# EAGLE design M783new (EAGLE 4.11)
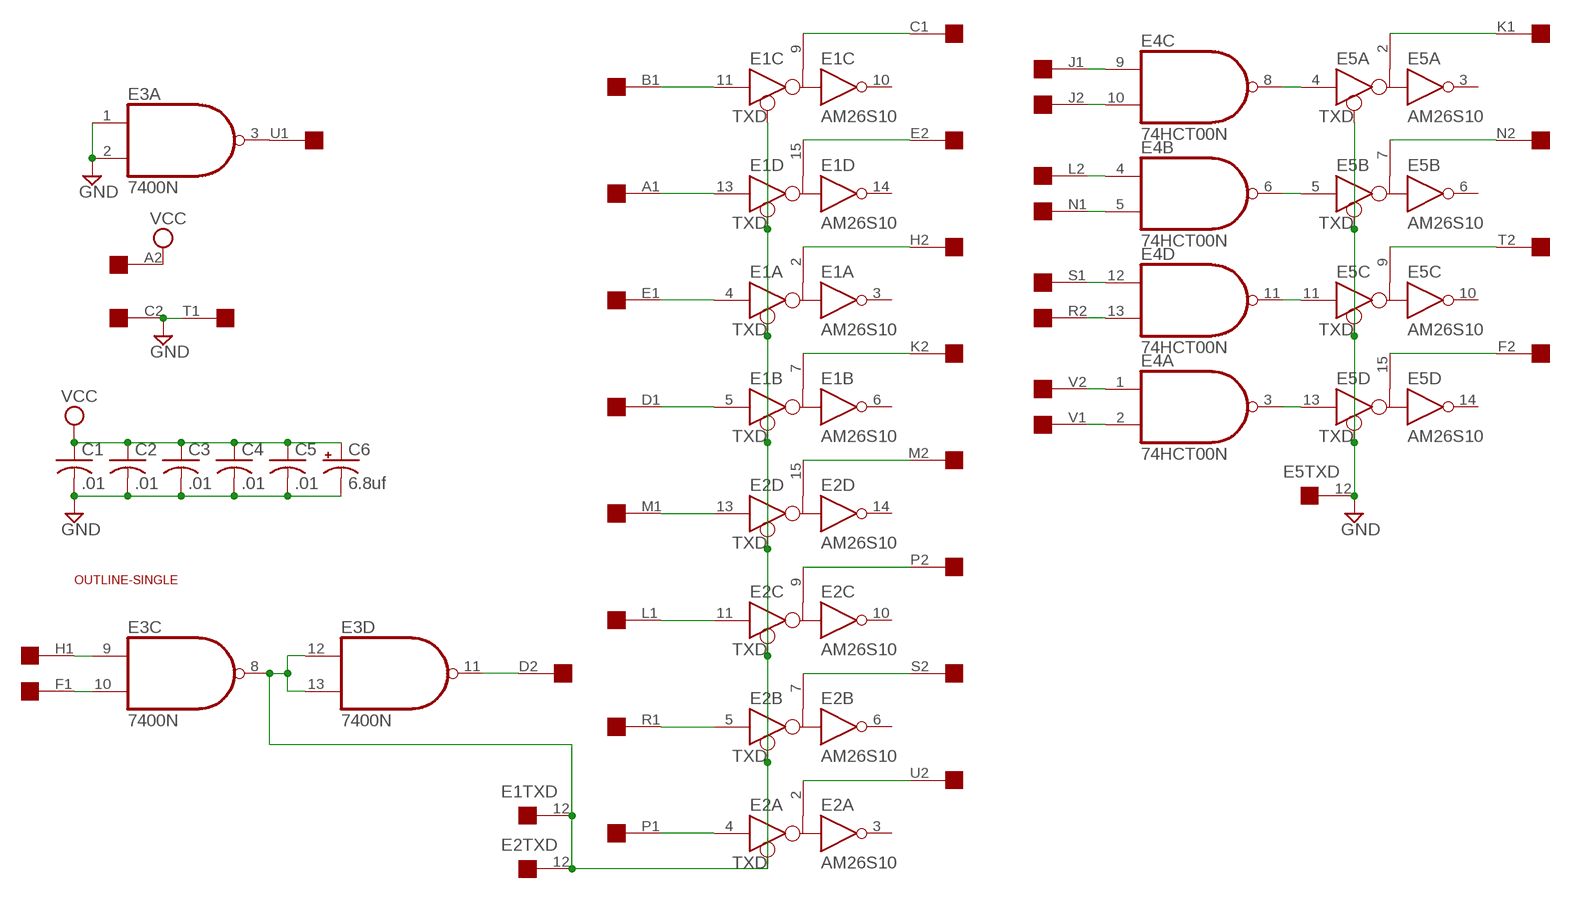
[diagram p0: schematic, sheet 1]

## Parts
C1  .01  C-US050-025X075  [C050-025X075]
C2  .01  C-US050-025X075  [C050-025X075]
C3  .01  C-US050-025X075  [C050-025X075]
C4  .01  C-US050-025X075  [C050-025X075]
C5  .01  C-US050-025X075  [C050-025X075]
C6  6.8uf  CPOL-USE15-5AXIAL  [E15-5]
E1  AM26S10  [DIL16]
E2  AM26S10  [DIL16]
E3  7400N  [DIL14]
E4  74HCT00N  [DIL14]
E5  AM26S10  [DIL16]
U$1  SINGLE  [EDGE-CON2]
U$2  OUTLINE-SINGLE  [SINGLE]

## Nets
GND: C1.2 C2.2 C3.2 C4.2 C5.2 C6.- E3.1(A:I0) E3.2(A:I1) E5.12(TXD:TXD) U$1.C2 U$1.T1
N$1: E3.3(A:O) U$1.U1
N$2: E1.12(TXD:TXD) E2.12(TXD:TXD) E3.8(C:O) E3.12(D:I0) E3.13(D:I1)
N$3: E2.15(D:B) U$1.M2
N$4: E2.9(C:B) U$1.P2
N$5: E2.4(A:D) U$1.P1
N$6: E2.5(B:D) U$1.R1
N$7: E2.7(B:B) U$1.S2
N$8: E2.11(C:D) U$1.L1
N$9: E2.2(A:B) U$1.U2
N$10: E2.13(D:D) U$1.M1
N$11: E1.9(C:B) U$1.C1
N$12: E1.11(C:D) U$1.B1
N$13: E1.15(D:B) U$1.E2
N$14: E1.13(D:D) U$1.A1
N$15: E1.2(A:B) U$1.H2
N$16: E1.4(A:D) U$1.E1
N$17: E1.7(B:B) U$1.K2
N$18: E1.5(B:D) U$1.D1
N$19: E3.11(D:O) U$1.D2
N$20: E5.7(B:B) U$1.N2
N$21: E5.9(C:B) U$1.T2
N$22: E5.15(D:B) U$1.F2
N$23: E5.2(A:B) U$1.K1
N$24: E4.9(C:I0) U$1.J1
N$25: E4.10(C:I1) U$1.J2
N$26: E4.4(B:I0) U$1.L2
N$27: E4.5(B:I1) U$1.N1
N$28: E4.12(D:I0) U$1.S1
N$29: E4.13(D:I1) U$1.R2
N$31: E3.9(C:I0) U$1.H1
N$32: E3.10(C:I1) U$1.F1
N$33: E4.1(A:I0) U$1.V2
N$34: E4.2(A:I1) U$1.V1
N$35: E4.8(C:O) E5.4(A:D)
N$36: E4.6(B:O) E5.5(B:D)
N$37: E4.11(D:O) E5.11(C:D)
N$38: E4.3(A:O) E5.13(D:D)
VCC: C1.1 C2.1 C3.1 C4.1 C5.1 C6.+ U$1.A2
Unconnected: E1.3(A:R) E1.6(B:R) E1.10(C:R) E1.14(D:R) E2.3(A:R) E2.6(B:R) E2.10(C:R) E2.14(D:R) E3.4(B:I0) E3.5(B:I1) E3.6(B:O) E5.3(A:R) E5.6(B:R) E5.10(C:R) E5.14(D:R) U$1.B2

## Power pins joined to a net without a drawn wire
GND: E1.1(GND:GND) E1.8(PWR:GND) E2.1(GND:GND) E2.8(PWR:GND) E3.7(P:GND) E4.7(P:GND) E5.1(GND:GND) E5.8(PWR:GND)
VCC: E1.16(PWR:VCC) E2.16(PWR:VCC) E3.14(P:VCC) E4.14(P:VCC) E5.16(PWR:VCC)

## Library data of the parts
C1-C5 = rcl:C-US: CAPACITOR, American symbol
C6 = rcl:CPOL-US: POLARIZED CAPACITOR, American symbol
E1 E2 E5 = dec-con:AM26S10: Bus Transceiver
E3 E4 = 74xx-jameco:74*00: Quad 2-input NAND gate
U$1 = dec-con:SINGLE: Single-Height DEC board
U$2 = dec-con:OUTLINE-*: Board outlines for DEC boards.

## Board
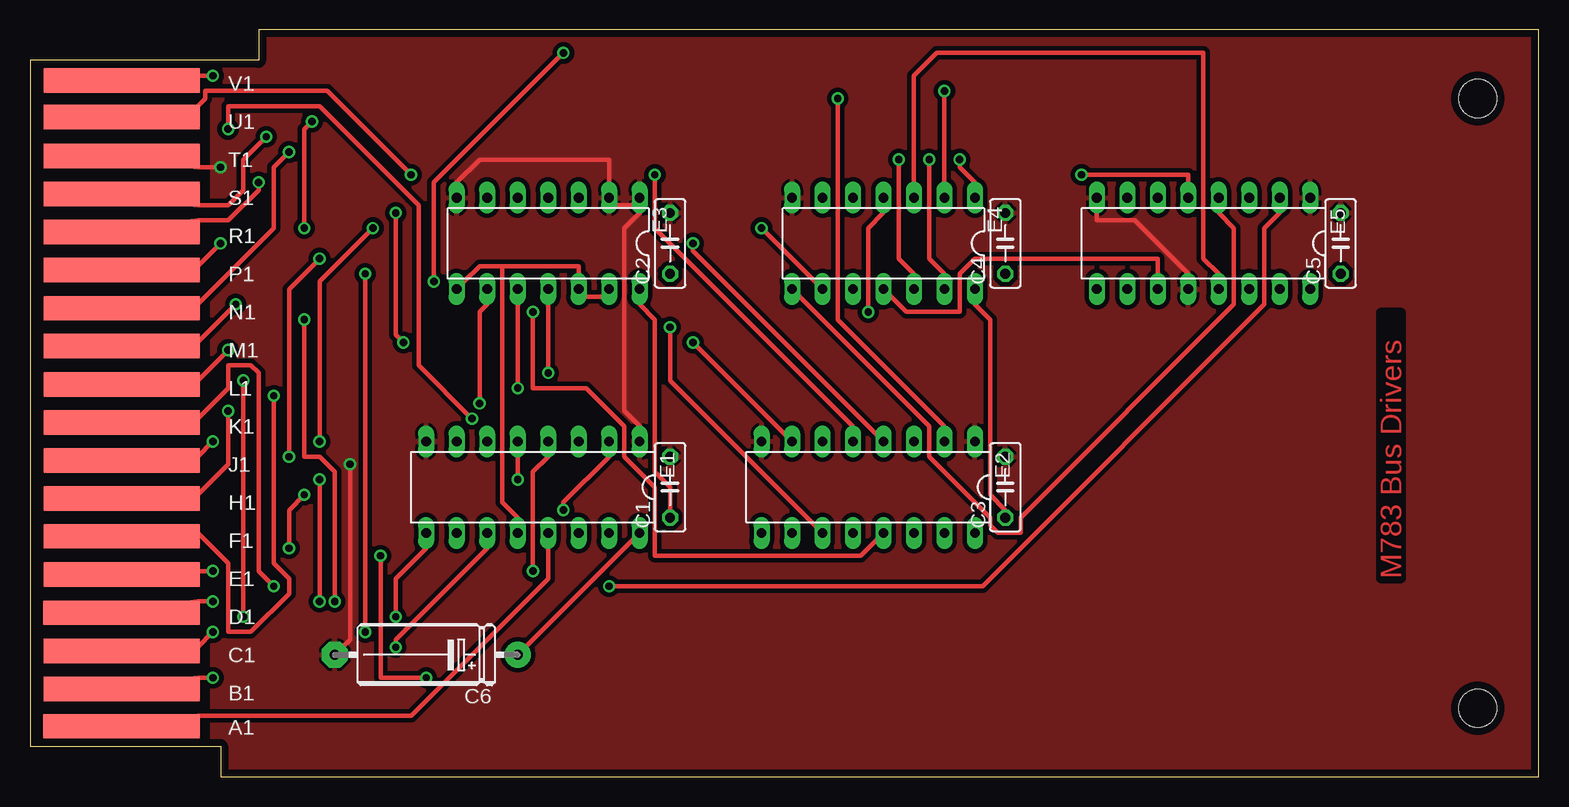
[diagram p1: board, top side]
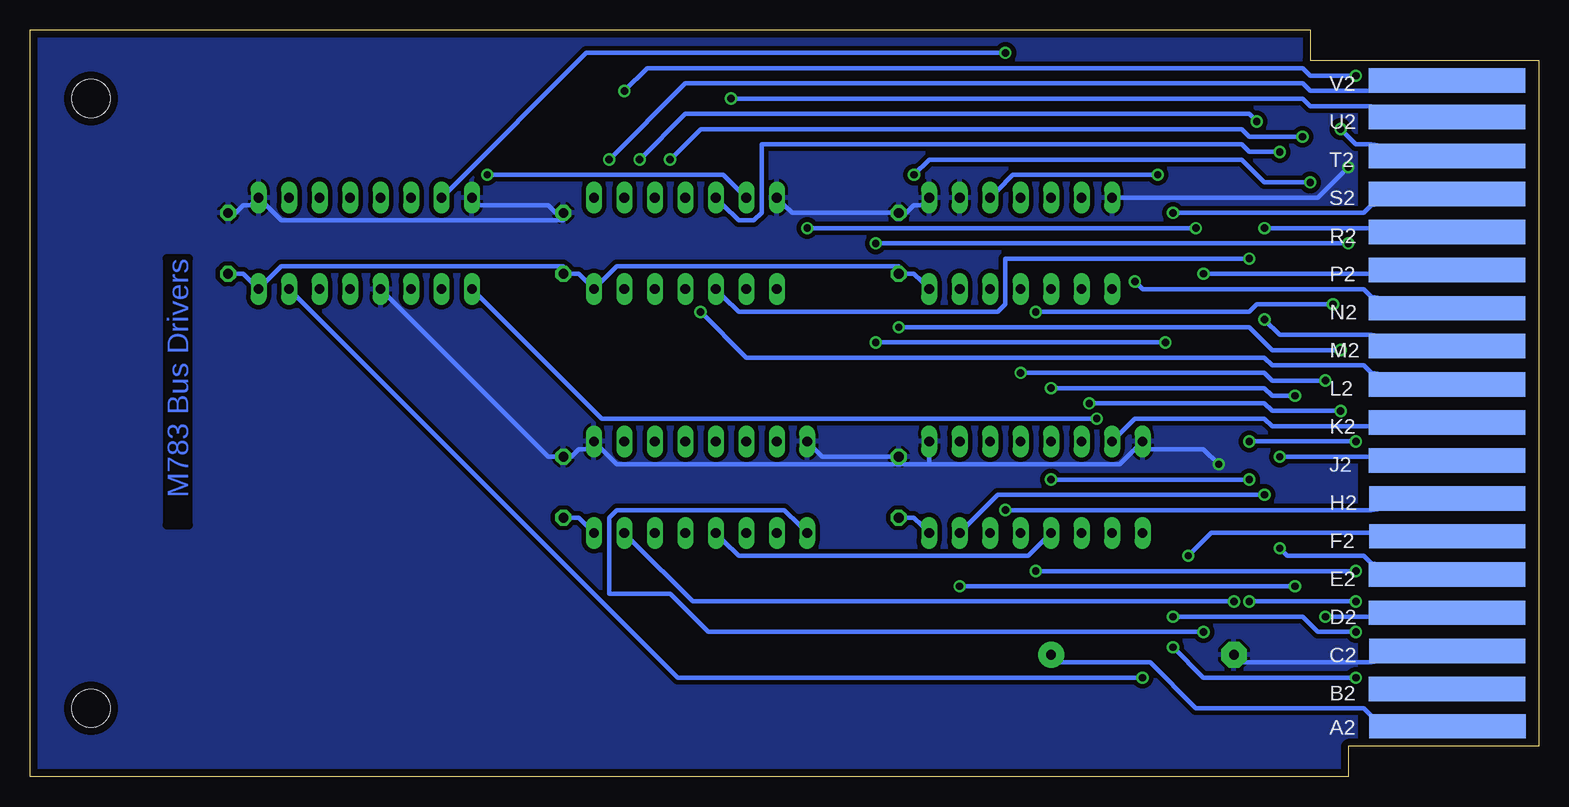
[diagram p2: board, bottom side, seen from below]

Size 125.73 x 62.23 mm. Coordinates in mm from the lower left corner, seen from the top.
Copper layers (1*16): Top 0.035mm / dielectric 1.5mm / Bottom 0.035mm
Design rules "15mils": minimum track width 15mil, minimum drill 24mil, track to track 15mil, track to pad 10mil, pad to pad 10mil, via to via 10mil, smd to smd 10mil, copper to edge 25mil, drill to drill 10mil, minimum pad ring 10mil, minimum via ring 8mil, stop-mask expansion 0mil, vias tented up to drill 0mil, thermal gap 10mil

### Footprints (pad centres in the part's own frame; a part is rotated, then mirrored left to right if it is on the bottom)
C050-025X075 = drill 0.813 octagon: 1 -2.54,0; 2 2.54,0
E15-5 = drill 0.813 pad 2.159 round: + -7.62,0 | drill 0.813 pad 2.159 octagon: - 7.62,0
DIL16 = drill 0.813 long: 1 -8.89,-3.81; 2 -6.35,-3.81; 3 -3.81,-3.81; 4 -1.27,-3.81; 5 1.27,-3.81; 6 3.81,-3.81; 7 6.35,-3.81; 8 8.89,-3.81; 9 8.89,3.81; 10 6.35,3.81; 11 3.81,3.81; 12 1.27,3.81; 13 -1.27,3.81; 14 -3.81,3.81; 15 -6.35,3.81; 16 -8.89,3.81
DIL14 = drill 0.813 long: 1 -7.62,-3.81; 2 -5.08,-3.81; 3 -2.54,-3.81; 4 0,-3.81; 5 2.54,-3.81; 6 5.08,-3.81; 7 7.62,-3.81; 8 7.62,3.81; 9 5.08,3.81; 10 2.54,3.81; 11 0,3.81; 12 -2.54,3.81; 13 -5.08,3.81; 14 -7.62,3.81
EDGE-CON2 = smd 13.017 x 2.032: A1 7.633,4.207; B1 7.639,7.327; C1 7.636,10.489; D1 7.633,13.665; E1 7.642,16.84; F1 7.642,20.041; H1 7.642,23.19; J1 7.642,26.34; K1 7.642,29.515; L1 7.642,32.69; M1 7.642,35.89; N1 7.642,39.04; P1 7.642,42.24; R1 7.642,45.39; S1 7.642,48.565; T1 7.642,51.74; U1 7.642,54.966; V1 7.642,58.026 | smd 13.017 x 2.032 bottom: A2 7.614,4.207; B2 7.642,7.328; C2 7.617,10.49; D2 7.642,13.665; E2 7.642,16.84; F2 7.617,20.041; H2 7.617,23.19; J2 7.642,26.34; K2 7.642,29.515; L2 7.642,32.69; M2 7.642,35.89; N2 7.642,39.04; P2 7.642,42.24; R2 7.642,45.39; S2 7.642,48.565; T2 7.642,51.74; U2 7.642,54.966; V2 7.642,58.026
SINGLE = hole 3.175: 120.65,56.515; 120.65,5.715

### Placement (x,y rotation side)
C1  53.34,24.13 90 top
C2  53.34,44.45 90 top
C3  81.28,24.13 90 top
C4  81.28,44.45 90 top
C5  109.22,44.45 90 top
C6  33.02,10.16 180 top
E1  41.91,24.13 180 top
E2  69.85,24.13 180 top
E3  43.18,44.45 180 top
E4  71.12,44.45 180 top
E5  97.79,44.45 180 top
U$1  0,0 0 top
U$2  0,0 0 top

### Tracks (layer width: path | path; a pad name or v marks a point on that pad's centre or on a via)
GND  (via drill 0.61)
  Top 0.381: E5.12 96.52,41.91 92.08,46.35 88.9,46.35 88.9,46.99 E5.8 | E3.7 35.56,49.53 37.47,51.44 48.26,51.44 48.26,49.53 E3.2 48.9,47.62 50.17,47.62 E3.1 50.8,46.99 49.53,45.72 49.53,30.48 50.8,29.21 E1.1 | v15.88,50.8 13.97,50.8 U$1.T1 | v26.67,26.04 26.67,11.43 26.04,10.79 C6.-
  Bottom 0.381: C6.- 24.77,9.53 13.97,9.53 U$1.C2 | C5.2 108.59,46.99 107.95,47.62 107.32,47.62 E5.1 106.05,47.62 104.78,46.35 81.28,46.35 C4.2 81.92,46.99 82.55,47.62 88.27,47.62 E5.8 | E3.1 51.44,47.62 52.07,47.62 52.71,46.99 C2.2 53.98,46.99 62.23,46.99 62.87,47.62 E4.7 | 50.8,26.04 53.34,26.04 | 50.8,26.04 34.93,26.04 33.66,27.3 E1.8 32.39,27.3 27.94,27.3 v26.67,26.04 | 53.34,26.04 C1.2 | 50.8,26.04 50.8,26.67 E1.1 | E2.8 60.33,27.3 59.69,26.67 53.98,26.67 C1.2 | 53.34,26.04 76.84,26.04 78.11,27.3 E2.1 79.38,27.3 80.01,27.3 80.65,26.67 C3.2 81.92,26.67 82.55,26.67 95.89,40.01 E5.12 | 53.34,26.04 C1.2 | v15.88,50.8 18.42,48.26 34.93,48.26 E3.7
  pour Bottom (isolate 0.305): 15.24,62.23 125.73,62.23 125.73,0 15.24,0
  pour Top (isolate 0.305): 15.24,62.23 125.73,62.23 125.73,0 15.24,0
N$1  (via drill 0.61)
  Top 0.381: v31.75,50.16 24.77,57.15 14.61,57.15 14.61,56.52 13.97,55.88 U$1.U1
  Bottom 0.381: v31.75,50.16 43.82,50.16 45.09,48.9 E3.3
N$2
  Top 0.381: E3.13 47.63,40.01 46.36,40.01 E3.12 45.72,41.91 45.72,42.55 39.37,42.55 | 39.37,42.55 37.47,42.55 36.2,41.27 E3.8 | 39.37,42.55 39.37,22.86 40.64,21.59 E1.12
  Bottom 0.381: E1.12 41.28,19.68 42.55,18.41 66.68,18.41 67.95,19.68 E2.12
N$3  (via drill 0.61)
  Top 0.381: v25.4,14.61 25.4,25.4 24.13,26.67 22.86,26.67 v22.86,38.1
  Bottom 0.381: v25.4,14.61 70.49,14.61 75.57,19.68 E2.15 | v22.86,38.1 21.59,36.83 13.97,36.83 U$1.M2
N$4  (via drill 0.61)
  Top 0.381: v27.94,12.06 v27.94,41.91
  Bottom 0.381: v27.94,12.06 69.22,12.06 72.39,15.24 77.47,15.24 77.47,21.59 76.84,22.23 62.87,22.23 61.6,20.95 E2.9 | v27.94,41.91 13.97,41.91 U$1.P2
N$5  (via drill 0.61)
  Top 0.381: v55.25,44.45 55.25,43.81 70.49,28.57 E2.4 | v15.88,44.45 13.97,42.55 U$1.P1
  Bottom 0.381: v15.88,44.45 v55.25,44.45
N$6  (via drill 0.61)
  Top 0.381: v52.07,50.16 52.07,45.72 68.58,29.21 E2.5 | v19.05,49.53 19.05,48.9 16.51,46.35 13.97,46.35 U$1.R1
  Bottom 0.381: v52.07,50.16 50.8,51.44 24.77,51.44 22.86,49.53 v19.05,49.53
N$7  (via drill 0.61)
  Top 0.381: v55.25,36.2 62.87,28.57 E2.7 | v31.12,36.2 30.48,36.83 v30.48,46.99
  Bottom 0.381: v31.12,36.2 v55.25,36.2 | v30.48,46.99 14.61,46.99 13.97,47.62 U$1.S2
N$8  (via drill 0.61)
  Top 0.381: v53.34,37.47 53.34,33.02 65.41,20.95 E2.11 | v16.51,35.56 13.97,33.02 U$1.L1
  Bottom 0.381: v53.34,37.47 24.13,37.47 22.23,35.56 v16.51,35.56
N$9  (via drill 0.61)
  Top 0.381: v67.31,56.52 67.31,38.1 76.2,29.21 E2.2
  Bottom 0.381: v67.31,56.52 19.69,56.52 19.05,55.88 13.97,55.88 U$1.U2
N$10  (via drill 0.61)
  Top 0.381: v41.91,38.73 41.91,32.38 46.36,32.38 49.53,29.21 49.53,26.67 52.07,24.13 52.07,18.41 69.22,18.41 70.49,19.68 E2.13 | v17.15,39.37 13.97,36.2 U$1.M1
  Bottom 0.381: v41.91,38.73 24.13,38.73 23.5,39.37 v17.15,39.37
N$11  (via drill 0.61)
  Top 0.381: v30.48,13.34 30.48,16.51 33.02,19.05 E1.9 | v15.24,12.06 13.97,10.79 U$1.C1
  Bottom 0.381: v30.48,13.34 19.69,13.34 18.42,12.06 v15.24,12.06
N$12  (via drill 0.61)
  Top 0.381: v30.48,10.79 30.48,11.43 38.1,19.05 E1.11 | v15.24,8.26 13.97,8.26 U$1.B1
  Bottom 0.381: v30.48,10.79 27.94,8.26 v15.24,8.26
N$13  (via drill 0.61)
  Top 0.381: v22.86,23.5 21.59,22.23 v21.59,19.05
  Bottom 0.381: v22.86,23.5 45.09,23.5 47.63,20.95 E1.15 | v21.59,19.05 20.96,18.41 14.61,18.41 13.97,17.78 U$1.E2
N$14
  Top 0.381: E1.13 43.18,19.05 43.18,16.51 31.75,5.08 13.97,5.08 U$1.A1
N$15  (via drill 0.61)
  Top 0.381: v44.45,22.23 44.45,22.86 48.26,26.67 E1.2
  Bottom 0.381: v44.45,22.23 13.97,22.23 U$1.H2
N$16  (via drill 0.61)
  Top 0.381: v41.91,17.14 41.91,25.4 43.18,26.67 E1.4 | v15.24,17.14 13.97,17.14 U$1.E1
  Bottom 0.381: v15.24,17.14 v41.91,17.14
N$17
  Bottom 0.381: E1.7 34.93,28.57 33.66,29.84 22.86,29.84 22.23,29.21 13.97,29.21 U$1.K2
N$18  (via drill 0.61)
  Top 0.381: v40.64,24.77 40.64,26.67 E1.5 | v24.13,14.61 v24.13,24.77 | v15.24,14.61 13.97,14.61 U$1.D1
  Bottom 0.381: v24.13,24.77 v40.64,24.77 | v15.24,14.61 v24.13,14.61
N$19  (via drill 0.61)
  Top 0.381: v43.18,33.66 43.18,39.37 E3.11 | v17.78,13.34 v17.78,33.02
  Bottom 0.381: v43.18,33.66 22.86,33.66 22.23,33.02 v17.78,33.02 | v17.78,13.34 13.97,13.34 U$1.D2
N$20  (via drill 0.61)
  Top 0.381: v44.45,60.33 33.66,49.53 v33.66,41.27
  Bottom 0.381: v44.45,60.33 79.38,60.33 90.81,48.9 E5.7 | v33.66,41.27 33.02,40.64 14.61,40.64 13.97,40.01 U$1.N2
N$21  (via drill 0.61)
  Top 0.381: v36.83,29.84 32.39,34.29 32.39,47.62 24.13,55.88 16.51,55.88 v16.51,53.98
  Bottom 0.381: v36.83,29.84 78.11,29.84 88.27,40.01 E5.9 | v16.51,53.98 15.24,52.7 13.97,52.7 U$1.T2
N$22  (via drill 0.61)
  Top 0.381: v33.02,8.26 29.21,8.26 v29.21,18.41
  Bottom 0.381: v33.02,8.26 71.76,8.26 103.51,40.01 E5.15 | v29.21,18.41 27.31,20.32 13.97,20.32 U$1.F2
N$23  (via drill 0.61)
  Top 0.381: v48.26,15.88 79.38,15.88 102.87,39.37 102.87,45.72 104.14,46.99 E5.2 | v20.32,15.88 19.05,17.14 19.05,33.66 18.42,34.29 16.51,34.29 16.51,32.38 13.97,29.84 U$1.K1
  Bottom 0.381: v20.32,15.88 v48.26,15.88
N$24  (via drill 0.61)
  Top 0.381: v60.96,45.72 65.41,41.27 E4.9 | v28.58,45.72 24.13,41.27 v24.13,27.94 | v15.24,27.94 13.97,26.67 U$1.J1
  Bottom 0.381: v28.58,45.72 v60.96,45.72 | v15.24,27.94 v24.13,27.94
N$25  (via drill 0.61)
  Top 0.381: v24.13,43.18 21.59,40.64 v21.59,26.67
  Bottom 0.381: v24.13,43.18 44.45,43.18 44.45,39.37 45.09,38.73 66.68,38.73 67.95,40.01 E4.10 | v21.59,26.67 13.97,26.67 U$1.J2
N$26  (via drill 0.61)
  Top 0.381: v69.85,38.73 69.85,45.72 71.12,46.99 E4.4
  Bottom 0.381: v69.85,38.73 66.04,34.92 22.86,34.92 22.23,34.29 14.61,34.29 13.97,33.66 U$1.L2
N$27  (via drill 0.61)
  Top 0.381: v21.59,52.07 20.32,50.8 20.32,45.72 13.97,39.37 U$1.N1
  Bottom 0.381: v21.59,52.07 24.13,52.07 24.77,52.7 64.77,52.7 64.77,46.99 65.41,46.35 66.68,46.35 67.95,47.62 E4.5
N$28  (via drill 0.61)
  Top 0.381: v72.39,51.44 72.39,43.18 73.66,41.91 E4.12 | v19.69,53.34 17.78,51.44 17.78,48.9 16.51,47.62 13.97,47.62 U$1.S1
  Bottom 0.381: v72.39,51.44 69.85,53.98 24.77,53.98 24.13,53.34 v19.69,53.34
N$29  (via drill 0.61)
  Top 0.381: v74.93,51.44 74.93,43.18 76.2,41.91 E4.13 | v23.5,54.61 22.86,53.98 v22.86,45.72
  Bottom 0.381: v74.93,51.44 71.12,55.24 24.13,55.24 v23.5,54.61 | v22.86,45.72 13.97,45.72 U$1.R2
N$31  (via drill 0.61)
  Top 0.381: v37.47,31.11 37.47,38.73 38.1,39.37 E3.9 | v16.51,30.48 16.51,26.04 13.97,23.5 U$1.H1
  Bottom 0.381: v37.47,31.11 22.86,31.11 22.23,30.48 v16.51,30.48
N$32  (via drill 0.61)
  Top 0.381: v40.64,32.38 40.64,39.37 E3.10 | v20.32,31.75 20.32,17.78 21.59,16.51 21.59,15.24 18.42,12.06 16.51,12.06 16.51,17.78 13.97,20.32 U$1.F1
  Bottom 0.381: v40.64,32.38 22.86,32.38 22.23,31.75 v20.32,31.75
N$33  (via drill 0.61)
  Top 0.381: v77.47,51.44 77.47,50.8 78.74,49.53 E4.1
  Bottom 0.381: v77.47,51.44 71.12,57.78 19.69,57.78 19.05,57.15 13.97,57.15 U$1.V2
N$34  (via drill 0.61)
  Top 0.381: v76.2,57.15 76.2,49.53 E4.2 | v15.24,58.42 13.97,58.42 U$1.V1
  Bottom 0.381: v76.2,57.15 74.3,59.05 19.69,59.05 19.05,58.42 v15.24,58.42
N$35
  Top 0.381: E4.8 64.14,40.01 74.93,29.21 74.93,26.67 80.01,21.59 80.01,20.95 80.65,20.32 82.55,20.32 82.55,21.59 100.33,39.37 100.33,45.72 99.06,46.99 E5.4
N$36  (via drill 0.61)
  Top 0.381: v87.63,50.16 96.52,50.16 96.52,49.53 E5.5
  Bottom 0.381: v87.63,50.16 67.95,50.16 66.68,48.9 E4.6
N$37
  Top 0.381: E4.11 71.76,40.01 73.03,38.73 77.47,38.73 77.47,41.91 78.74,43.18 93.98,43.18 93.98,41.91 E5.11
N$38
  Top 0.381: E4.3 73.66,49.53 73.66,58.42 75.57,60.33 97.79,60.33 97.79,43.18 99.06,41.91 E5.13
VCC
  Top 0.381: C3.1 81.28,22.23 80.01,23.5 80.01,38.1 78.74,39.37 E4.14 | E1.16 50.17,19.68 41.28,10.79 C6.+ | E3.14 50.8,39.37 52.07,38.1 52.07,25.4 53.34,24.13 53.34,22.23 C1.1
  Bottom 0.381: C5.1 108.59,41.91 107.95,41.91 107.32,41.27 E5.16 106.05,41.27 104.78,42.55 81.28,42.55 C4.1 80.65,41.91 80.01,41.91 79.38,41.27 E4.14 78.11,41.27 76.84,42.55 53.34,42.55 C2.1 52.71,41.91 52.07,41.91 51.44,41.27 E3.14 | E2.16 79.38,20.95 80.01,21.59 80.65,21.59 C3.1 | E1.16 51.44,20.95 52.07,21.59 52.71,21.59 C1.1 | U$1.A2 13.97,5.08 14.61,5.71 28.58,5.71 32.39,9.53 40.01,9.53 C6.+

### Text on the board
Top: M783 Bus Drivers
Bottom: M783 Bus Drivers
